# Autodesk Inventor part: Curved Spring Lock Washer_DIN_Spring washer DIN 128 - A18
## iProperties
Shininess: 64.0
Length Units: 11269
Angle Units: 11279
Time Units: 11290
Mass Units: 11283
Length Display Precision: 3
Angle Display Precision: 2
Compacted: True
Part Number: Curved Spring Lock Washer_DIN_Spring washer DIN 128 - A18
Document SubType Name: Modeling
Created: 2006-11
Material: Par défaut
Designer: profs_sti
Density: 0.0
Volumn: 0.0
Area: 0.0
PropertySet Name: Model Information
Control State: 0
Master: False
Checked Out: False
Author: profs_sti
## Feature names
1. Base1
